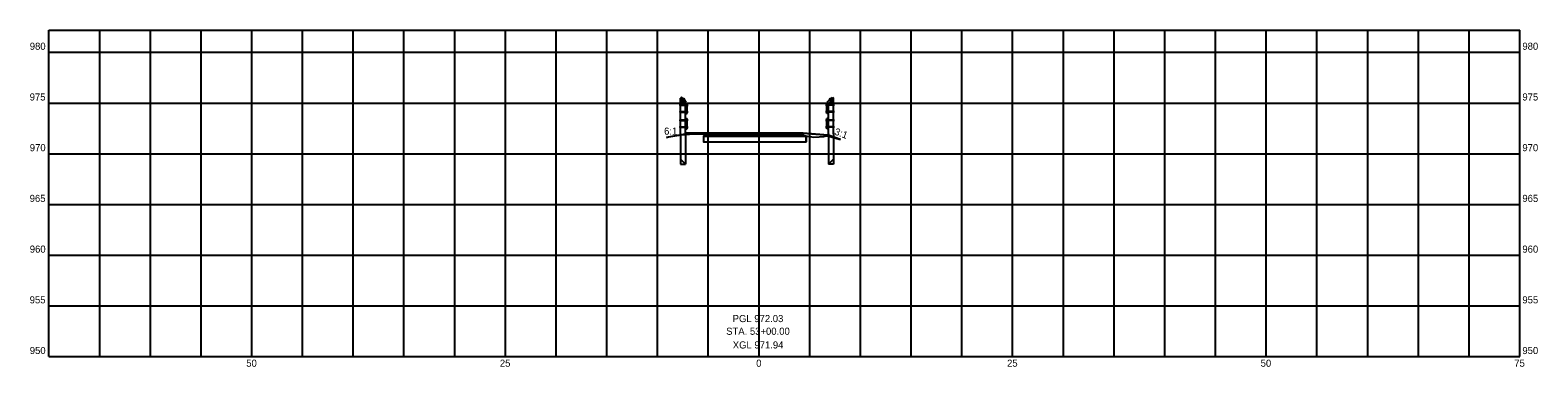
# Model space of a CAD drawing. Extents: x -72 to 77, y 949 to 982.
import ezdxf

# ---------------------------------------------------------------- set-up
doc = ezdxf.new("R2010")
doc.units = 0
for name, color, linetype in [('_CIVIL_CONSTRUCTION', 7, 'Continuous'), ('Default', 7, 'Continuous'), ('DT_X_Contour_Minor', 7, 'Continuous'), ('DT_X_Triangles', 7, 'Continuous'), ('GE_X_Alignment_500_Distances', 7, 'Continuous'), ('SH_Major_Grid_Line', 7, 'Continuous'), ('SH_Text', 7, 'Continuous'), ('XS_P_Finished_Grade', 7, 'Continuous')]:
    doc.layers.add(name, color=color, linetype=linetype)

msp = doc.modelspace()

# ---------------------------------------------------------------- linework, layer by layer
at = {"layer": '_CIVIL_CONSTRUCTION'}
msp.add_circle((0, 971.95), 0.05, dxfattribs=at)
at = {"layer": 'Default'}
for p, q in [((-7.64, 975.59), (-7.75, 975.47)), ((-7.75, 971.97), (-7.75, 975.47)), ((-7.75, 975.47), (-7.75, 975.47)), ((-7.25, 974.97), (-7.75, 975.47)), ((-7.33, 975.39), (-7.75, 974.97)), ((-7.66, 975), (-7.73, 975.07)), ((-7.42, 975.37), (-7.72, 975.07)), ((-7.35, 975.31), (-7.66, 975)), ((-7.14, 975.09), (-7.64, 975.59)), ((-7.25, 974.97), (-7.14, 975.09)), ((6.73, 975.09), (7.23, 975.59)), ((6.84, 974.97), (6.73, 975.09)), ((6.84, 974.97), (7.34, 975.47)), ((6.92, 975.39), (7.34, 974.97)), ((6.94, 975.31), (7.25, 975)), ((7.01, 975.37), (7.31, 975.07)), ((7.23, 975.59), (7.34, 975.47)), ((7.25, 975), (7.31, 975.07)), ((7.34, 971.97), (7.34, 975.47)), ((7.34, 975.47), (7.34, 975.47)), ((-7.84, 974.8), (-6.97, 974.8)), ((-7.84, 974.13), (-6.97, 974.13)), ((-7.79, 974.82), (-7.09, 974.82)), ((-7.79, 974.78), (-7.79, 974.82)), ((-7.79, 974.78), (-7.09, 974.78)), ((-7.79, 974.16), (-7.09, 974.16)), ((-7.79, 974.11), (-7.79, 974.16)), ((-7.79, 974.11), (-7.09, 974.11)), ((-7.77, 974.76), (-7.77, 974.84)), ((-7.77, 974.84), (-7.75, 974.84)), ((-7.77, 974.76), (-7.75, 974.76)), ((-7.77, 974.09), (-7.77, 974.18)), ((-7.77, 974.18), (-7.75, 974.18)), ((-7.77, 974.09), (-7.75, 974.09)), ((-7.25, 971.97), (-7.25, 974.97)), ((-7.25, 974.97), (-7.09, 974.97)), ((-7.25, 973.97), (-7.09, 973.97)), ((-7.09, 973.97), (-7.09, 974.97)), ((7.43, 974.8), (6.56, 974.8)), ((7.43, 974.13), (6.56, 974.13)), ((6.68, 973.97), (6.68, 974.97)), ((6.84, 974.97), (6.68, 974.97)), ((7.38, 974.82), (6.68, 974.82)), ((7.38, 974.78), (6.68, 974.78)), ((7.38, 974.16), (6.68, 974.16)), ((7.38, 974.11), (6.68, 974.11)), ((6.84, 973.97), (6.68, 973.97)), ((6.84, 971.97), (6.84, 974.97)), ((7.36, 974.84), (7.34, 974.84)), ((7.36, 974.76), (7.34, 974.76)), ((7.36, 974.18), (7.34, 974.18)), ((7.36, 974.09), (7.34, 974.09)), ((7.36, 974.76), (7.36, 974.84)), ((7.36, 974.09), (7.36, 974.18)), ((7.38, 974.78), (7.38, 974.82)), ((7.38, 974.11), (7.38, 974.16)), ((-6.97, 973.3), (-7.84, 973.3)), ((-7.84, 972.63), (-6.97, 972.63)), ((-7.79, 973.32), (-7.09, 973.32)), ((-7.79, 973.28), (-7.79, 973.32)), ((-7.79, 973.28), (-7.09, 973.28)), ((-7.79, 972.66), (-7.09, 972.66)), ((-7.79, 972.61), (-7.79, 972.66)), ((-7.79, 972.61), (-7.09, 972.61)), ((-7.77, 973.26), (-7.77, 973.34)), ((-7.77, 973.34), (-7.75, 973.34)), ((-7.77, 973.26), (-7.75, 973.26)), ((-7.77, 972.59), (-7.77, 972.68)), ((-7.77, 972.68), (-7.75, 972.68)), ((-7.77, 972.59), (-7.75, 972.59)), ((-7.25, 973.47), (-7.09, 973.47)), ((-7.25, 972.47), (-7.09, 972.47)), ((-5.19, 972.04), (-7.25, 972.04)), ((-7.25, 972.04), (-7.25, 968.97)), ((-7.09, 972.47), (-7.09, 973.47)), ((6.56, 973.3), (7.43, 973.3)), ((7.43, 972.63), (6.56, 972.63)), ((6.84, 973.47), (6.68, 973.47)), ((6.68, 972.47), (6.68, 973.47)), ((7.38, 973.32), (6.68, 973.32)), ((7.38, 973.28), (6.68, 973.28)), ((7.38, 972.66), (6.68, 972.66)), ((7.38, 972.61), (6.68, 972.61)), ((6.84, 972.47), (6.68, 972.47)), ((7.36, 973.34), (7.34, 973.34)), ((7.36, 973.26), (7.34, 973.26)), ((7.36, 972.68), (7.34, 972.68)), ((7.36, 972.59), (7.34, 972.59)), ((7.36, 973.26), (7.36, 973.34)), ((7.36, 972.59), (7.36, 972.68)), ((7.38, 973.28), (7.38, 973.32)), ((7.38, 972.61), (7.38, 972.66)), ((-7.75, 971.97), (-7.75, 968.97)), ((-7.25, 971.97), (-7.25, 968.97)), ((6.84, 971.97), (6.84, 968.97)), ((7.34, 971.97), (7.34, 968.97)), ((-7.75, 969.47), (-7.25, 968.97)), ((7.34, 969.47), (6.84, 968.97)), ((-7.75, 968.97), (-7.25, 968.97)), ((7.34, 968.97), (6.84, 968.97))]:
    msp.add_line(p, q, dxfattribs=at)
for centre, radius, start, end in [((-7.57, 975.16), 0.298, 17.3562, 70.8273), ((7.16, 975.16), 0.298, 109.1727, 162.6438), ((-7.12, 974.8), 0.0628, 298.9017, 61.0983), ((-7.12, 974.13), 0.0628, 298.9017, 61.0983), ((6.71, 974.8), 0.0628, 118.9017, 241.0983), ((6.71, 974.13), 0.0628, 118.9017, 241.0983), ((-7.12, 973.3), 0.0628, 298.9017, 61.0983), ((-7.12, 972.63), 0.0628, 298.9017, 61.0983), ((6.71, 973.3), 0.0628, 118.9017, 241.0983), ((6.71, 972.63), 0.0628, 118.9017, 241.0983)]:
    msp.add_arc(centre, radius, start, end, dxfattribs=at)
at = {"layer": 'DT_X_Contour_Minor'}
msp.add_lwpolyline([(8.02, 971.42), (6.82, 971.82), (4.36, 972.02), (0, 972.03), (-5.19, 972.04), (-6.09, 971.97), (-5.19, 971.97), (-1.08, 971.96), (-0.51, 971.96), (0, 971.95), (2.2, 971.88), (4.36, 971.81), (5.4, 971.62), (5.93, 971.66), (6.38, 971.7), (6.53, 971.72), (6.74, 971.77)], close=True, dxfattribs=at)
at = {"layer": 'DT_X_Triangles'}
for points in [[(-9.11, 971.6), (-8.92, 971.67), (-7.25, 971.97), (-6.09, 971.97), (-7.69, 971.84)], [(-9.11, 971.6), (-8.92, 971.67), (-7.25, 971.97), (-6.09, 971.97), (-7.69, 971.84)], [(-5.19, 971.97), (-5.19, 971.74), (-5.47, 971.74), (-5.48, 971.17), (4.65, 971.16), (4.64, 971.73), (4.36, 971.73), (4.36, 971.81), (2.2, 971.88), (0, 971.95), (-1.84, 971.96)]]:
    msp.add_lwpolyline(points, close=True, dxfattribs=at)
at = {"layer": 'GE_X_Alignment_500_Distances'}
for p, q in [((-5.19, 972.04), (-7.69, 971.84)), ((4.36, 972.02), (6.86, 971.82))]:
    msp.add_line(p, q, dxfattribs=at)
at = {"layer": 'SH_Major_Grid_Line'}
for p, q in [((-70, 982.19), (75, 982.19)), ((-70, 950), (-70, 982.19)), ((-65, 950), (-65, 982.19)), ((-60, 950), (-60, 982.19)), ((-55, 950), (-55, 982.19)), ((-50, 950), (-50, 982.19)), ((-45, 950), (-45, 982.19)), ((-40, 950), (-40, 982.19)), ((-35, 950), (-35, 982.19)), ((-30, 950), (-30, 982.19)), ((-25, 950), (-25, 982.19)), ((-20, 950), (-20, 982.19)), ((-15, 950), (-15, 982.19)), ((-10, 950), (-10, 982.19)), ((-5, 950), (-5, 982.19)), ((0, 950), (0, 982.19)), ((5, 950), (5, 982.19)), ((10, 950), (10, 982.19)), ((15, 950), (15, 982.19)), ((20, 950), (20, 982.19)), ((25, 950), (25, 982.19)), ((30, 950), (30, 982.19)), ((35, 950), (35, 982.19)), ((40, 950), (40, 982.19)), ((45, 950), (45, 982.19)), ((50, 950), (50, 982.19)), ((55, 950), (55, 982.19)), ((60, 950), (60, 982.19)), ((65, 950), (65, 982.19)), ((70, 950), (70, 982.19)), ((75, 950), (75, 982.19)), ((-70, 980), (75, 980)), ((-70, 975), (75, 975)), ((-70, 970), (75, 970)), ((-70, 965), (75, 965)), ((-70, 960), (75, 960)), ((-70, 955), (75, 955)), ((-70, 950), (75, 950))]:
    msp.add_line(p, q, dxfattribs=at)
at = {"layer": 'SH_Text'}
for p, q in [((-5.19, 972.04), (-5.19, 971.74)), ((-5.47, 971.74), (-5.48, 971.17)), ((4.36, 972.02), (4.36, 971.87)), ((4.36, 971.87), (4.36, 971.73)), ((4.64, 971.73), (4.65, 971.17))]:
    msp.add_line(p, q, dxfattribs=at)
for points in [[(-5.19, 972.04), (0, 972.03), (4.36, 972.02)], [(-5.48, 971.17), (-0.01, 971.19), (4.63, 971.16)], [(-5.47, 971.74), (0, 971.75), (4.64, 971.73)], [(-5.19, 971.88), (0, 971.89), (4.36, 971.87)]]:
    msp.add_lwpolyline(points, dxfattribs=at)
at = {"layer": 'XS_P_Finished_Grade'}
for p, q in [((-7.69, 971.84), (-9.11, 971.6)), ((6.86, 971.81), (8.02, 971.42))]:
    msp.add_line(p, q, dxfattribs=at)

# ---------------------------------------------------------------- texts
at = {"layer": 'SH_Text'}
for s, p in [('980', (-71.89, 980.25)), ('980', (75.25, 980.25)), ('975', (-71.9, 975.25)), ('975', (75.25, 975.25)), ('6:1', (-9.36, 971.88)), ('970', (-71.89, 970.25)), ('970', (75.25, 970.25)), ('965', (-71.9, 965.25)), ('965', (75.25, 965.25)), ('960', (-71.89, 960.25)), ('960', (75.25, 960.25)), ('955', (-71.9, 955.25)), ('955', (75.25, 955.25)), ('STA. 53+00.00', (-3.24, 952.15)), ('PGL 972.03', (-2.6, 953.4)), ('XGL 971.94', (-2.59, 950.8)), ('950', (-71.89, 950.25)), ('950', (75.25, 950.25)), ('50', (-50.55, 949)), ('25', (-25.55, 949)), ('0', (-0.28, 949)), ('25', (24.45, 949)), ('50', (49.45, 949)), ('75', (74.45, 949))]:
    msp.add_text(s, height=0.7, dxfattribs=at).set_placement(p)
msp.add_text('3:1', height=0.7, rotation=339.4687, dxfattribs=at).set_placement((7.37, 971.91))

doc.saveas('drawing.dxf')
